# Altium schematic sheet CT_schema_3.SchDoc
size 357 x 214 mm
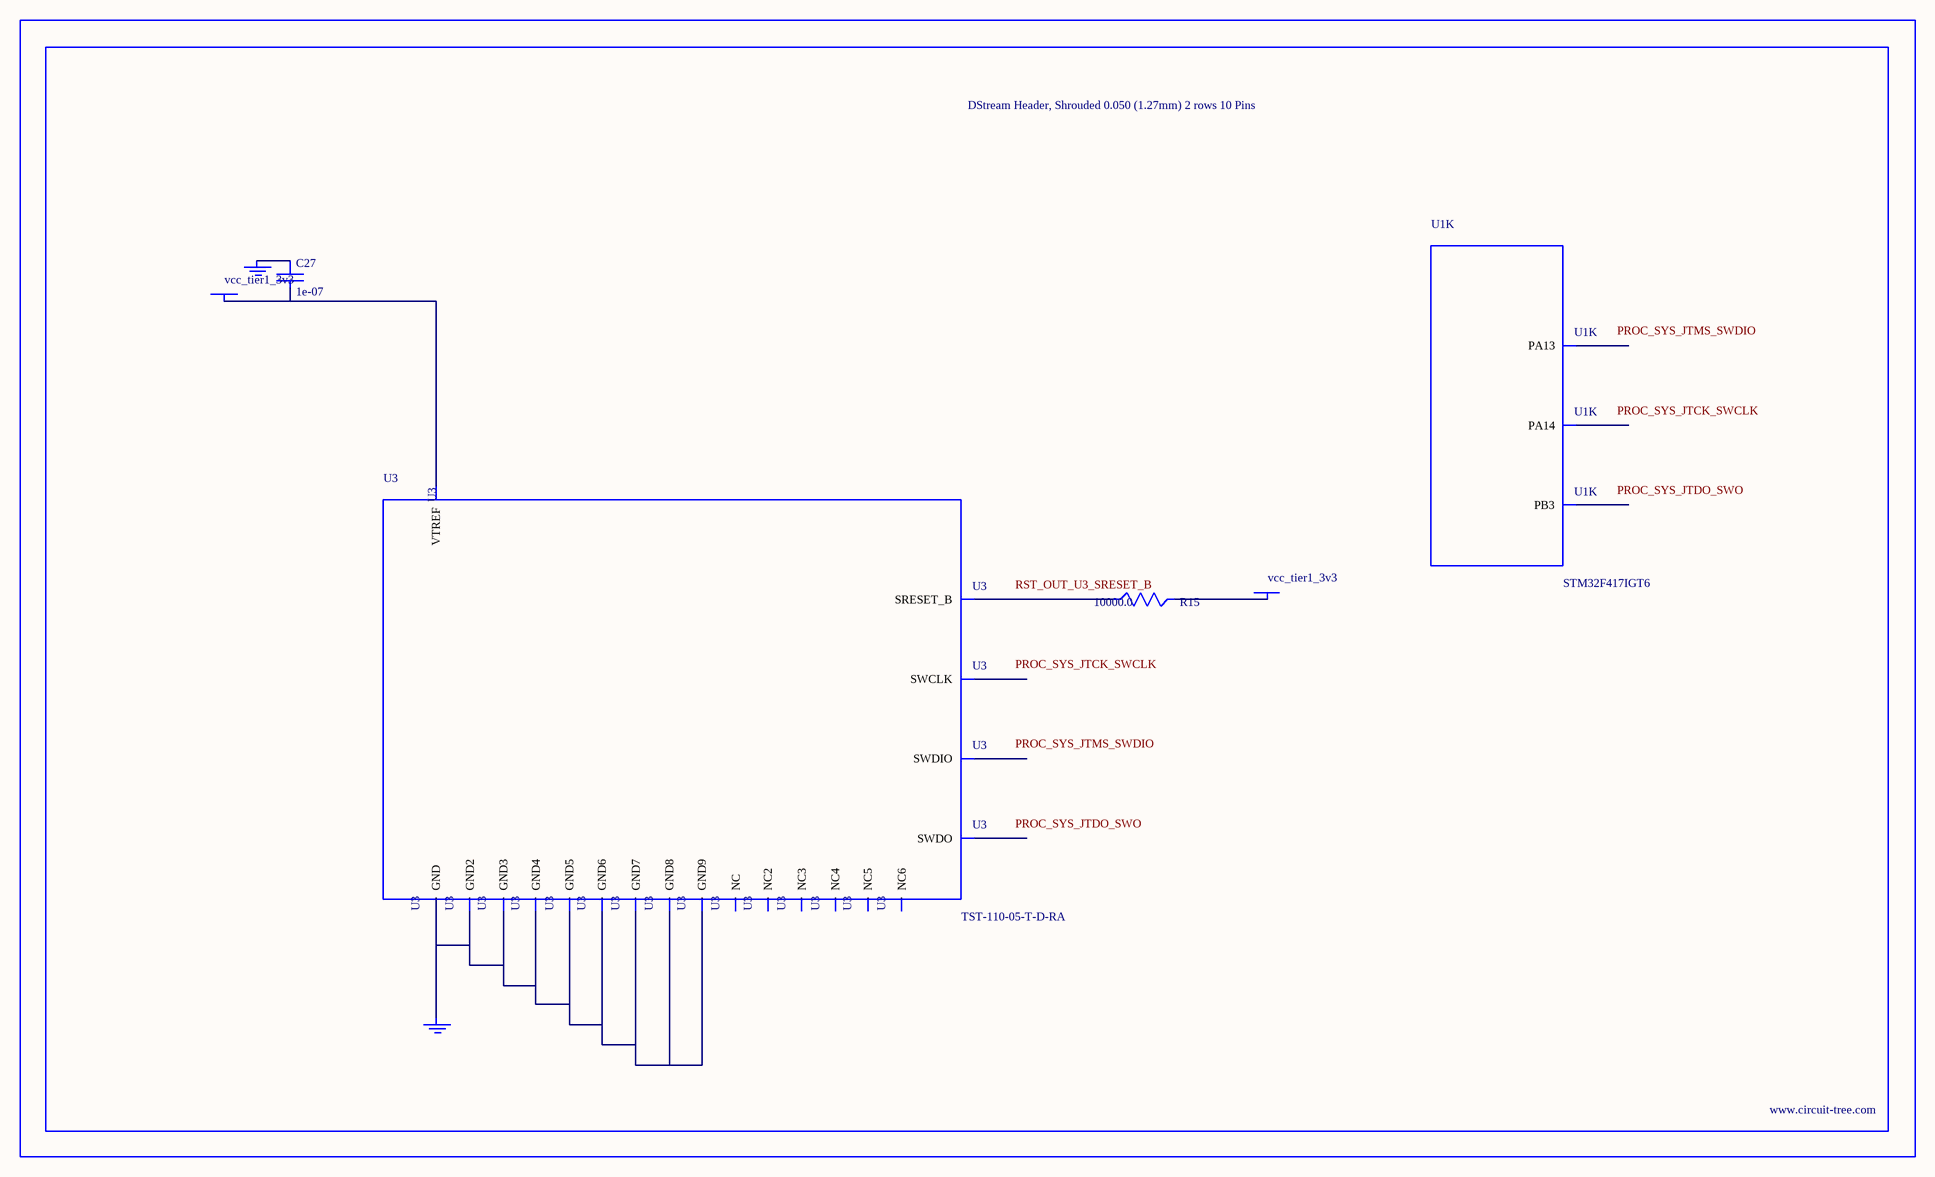
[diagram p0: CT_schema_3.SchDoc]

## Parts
BORDER2  (no value)
C27  1e-07  [C0402]
GND_INSTANCE_2_0  (no value)
GND_INSTANCE_2_1  (no value)
POWER_INSTANCE_2_0  vcc_tier1_3v3
POWER_INSTANCE_2_1  vcc_tier1_3v3
R15  10000.0  [R0603]
U1  STM32F417IGT6  [LQFP176]  (part K of 16)
U3  TST-110-05-T-D-RA  [TST-110-05-T-D-RA]

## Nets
NetC27_1: C27.1 GND_INSTANCE_2_0.0(GND)
NetC27_2: C27.2 POWER_INSTANCE_2_0.0(PWR) U3.1(VTREF)
NetGND_INSTANCE_2_1_0: GND_INSTANCE_2_1.0(GND) U3.4(GND) U3.6(GND2) U3.8(GND3) U3.10(GND4) U3.12(GND5) U3.14(GND6) U3.16(GND7) U3.18(GND8) U3.20(GND9)
NetPOWER_INSTANCE_2_1_0: POWER_INSTANCE_2_1.0(PWR) R15.2
NetR15_1: R15.1 U3.15(SRESET_B)

Not connected (* = marked no-connect by the designer): U1 124(PA13) 137(PA14) 161(PB3); U3 2(NC) 3(NC2) 5(NC3) 7(SWDIO) 9(SWCLK) 11(NC4) 13(SWDO) 17(NC5) 19(NC6)

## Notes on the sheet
- Labels drawn without touching a wire or pin: PROC_SYS_JTCK_SWCLK, PROC_SYS_JTDO_SWO, PROC_SYS_JTMS_SWDIO, RST_OUT_U3_SRESET_B

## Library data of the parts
BORDER2 = BORDER_PAGE2
C27 = C0402C104K3RACTU
GND_INSTANCE_2_0 GND_INSTANCE_2_1 = GND
POWER_INSTANCE_2_0 POWER_INSTANCE_2_1 = PWR
R15 = RC0603JR-0710KL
